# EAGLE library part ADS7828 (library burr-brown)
12-Bit, 8-Channel Sampling ANALOG-TO-DIGITAL CONVERTER with I2C? Interface Source: www.ti.com .. ADS7828.pdf
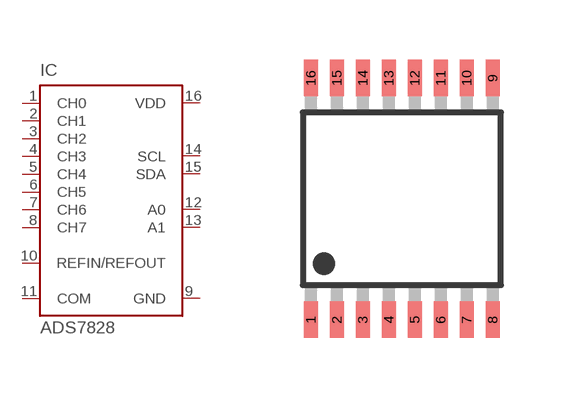
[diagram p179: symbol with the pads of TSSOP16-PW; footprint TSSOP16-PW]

Designator prefix IC

## ADS7828 (MF: TEXAS INSTRUMENTS; MPN: ADS7828E/250; OC_FARNELL: 1470338; OC_NEWARK: 74C7158)  [TSSOP16-PW]
1  CH0  in
2  CH1  in
3  CH2  in
4  CH3  in
5  CH4  in
6  CH5  in
7  CH6  in
8  CH7  in
9  GND  pwr
10  REFIN/REFOUT  pas
11  COM  in
12  A0  in
13  A1  in
14  SCL  in
15  SDA
16  VDD  pwr

## Footprint TSSOP16-PW (pad centres in mm)
PLASTIC SMALL-OUTLINE PACKAGE PW (R-PDSO-G16) Source: www.ti.com .. ADS7828.pdf
smd 0.35 x 0.9: 1 -2.275,-3.025; 2 -1.625,-3.025; 3 -0.975,-3.025; 4 -0.325,-3.025; 5 0.325,-3.025; 6 0.975,-3.025; 7 1.625,-3.025; 8 2.275,-3.025; 9 2.275,3.025; 10 1.625,3.025; 11 0.975,3.025; 12 0.325,3.025; 13 -0.325,3.025; 14 -0.975,3.025; 15 -1.625,3.025; 16 -2.275,3.025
